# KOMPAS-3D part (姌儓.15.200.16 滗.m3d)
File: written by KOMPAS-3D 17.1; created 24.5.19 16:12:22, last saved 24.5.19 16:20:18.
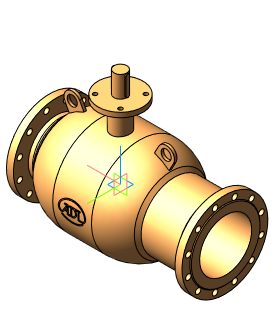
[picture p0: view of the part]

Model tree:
1. Операция без истории:1  (labels: Сталь 20  ГОСТ 1050-2013)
